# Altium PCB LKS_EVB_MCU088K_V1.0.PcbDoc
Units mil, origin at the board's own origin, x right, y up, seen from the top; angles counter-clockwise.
Board outline 2625 x 1560 mil, 2 copper layers (Top Layer, Bottom Layer); 36 components, 61 nets, 173 pads, 60 vias.
Unrouted connection lines stored in the file: 4.
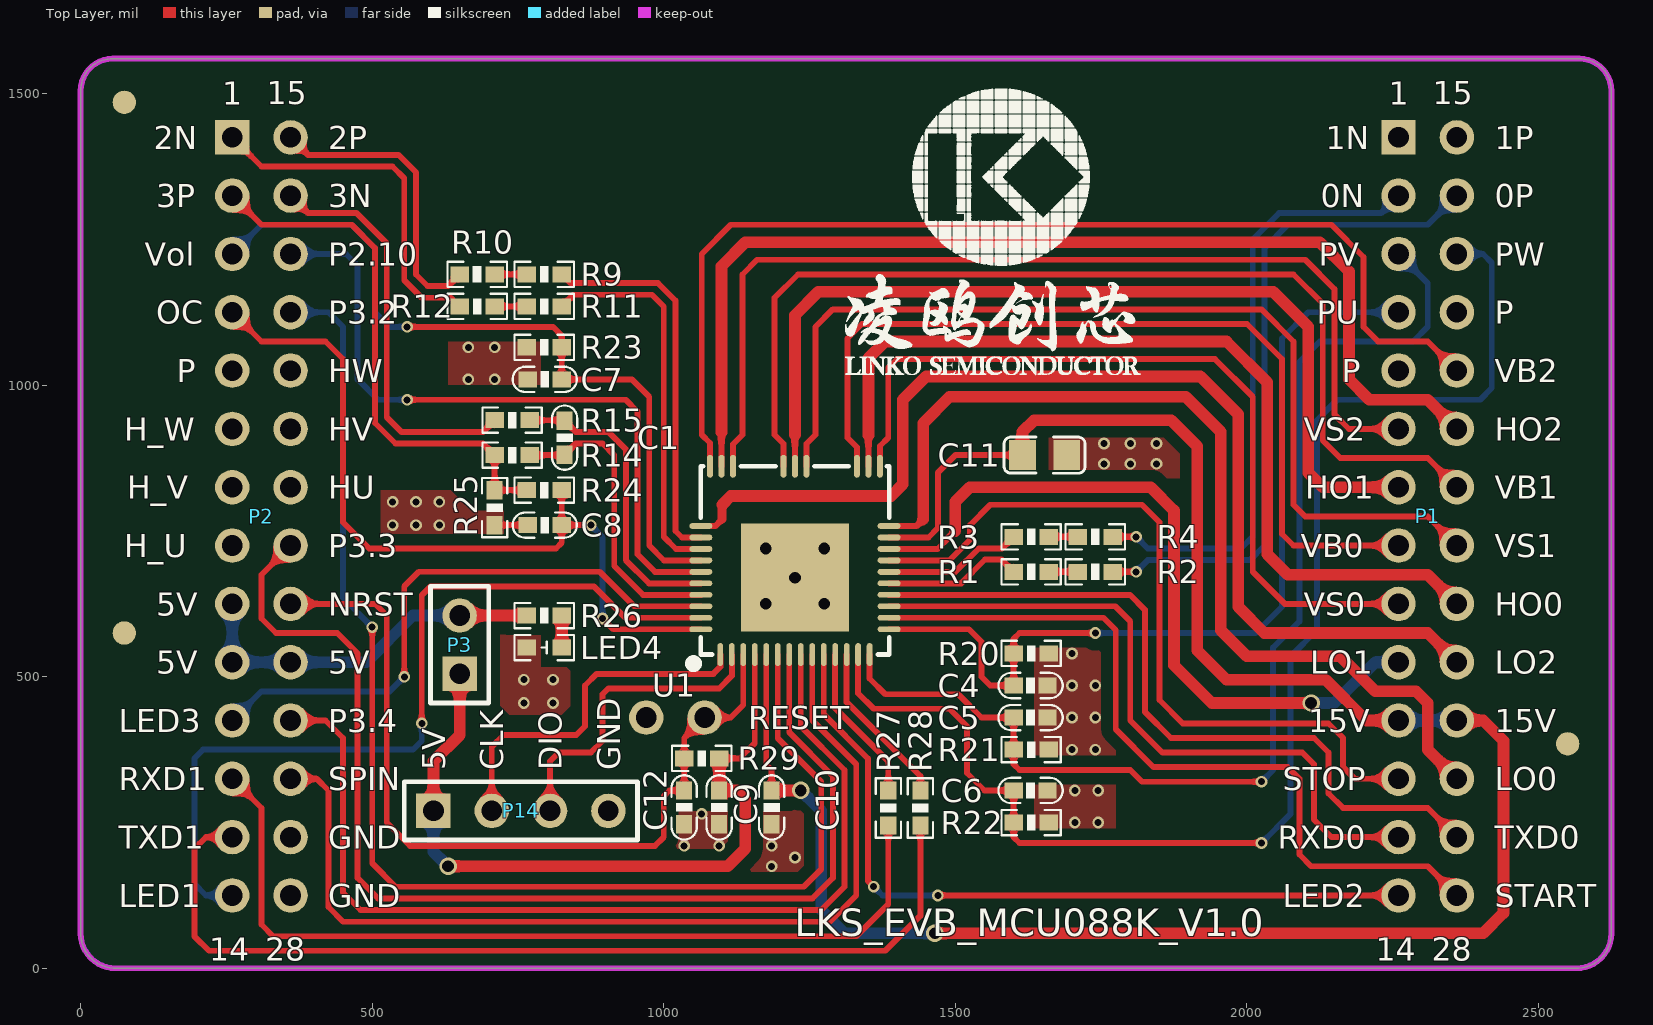
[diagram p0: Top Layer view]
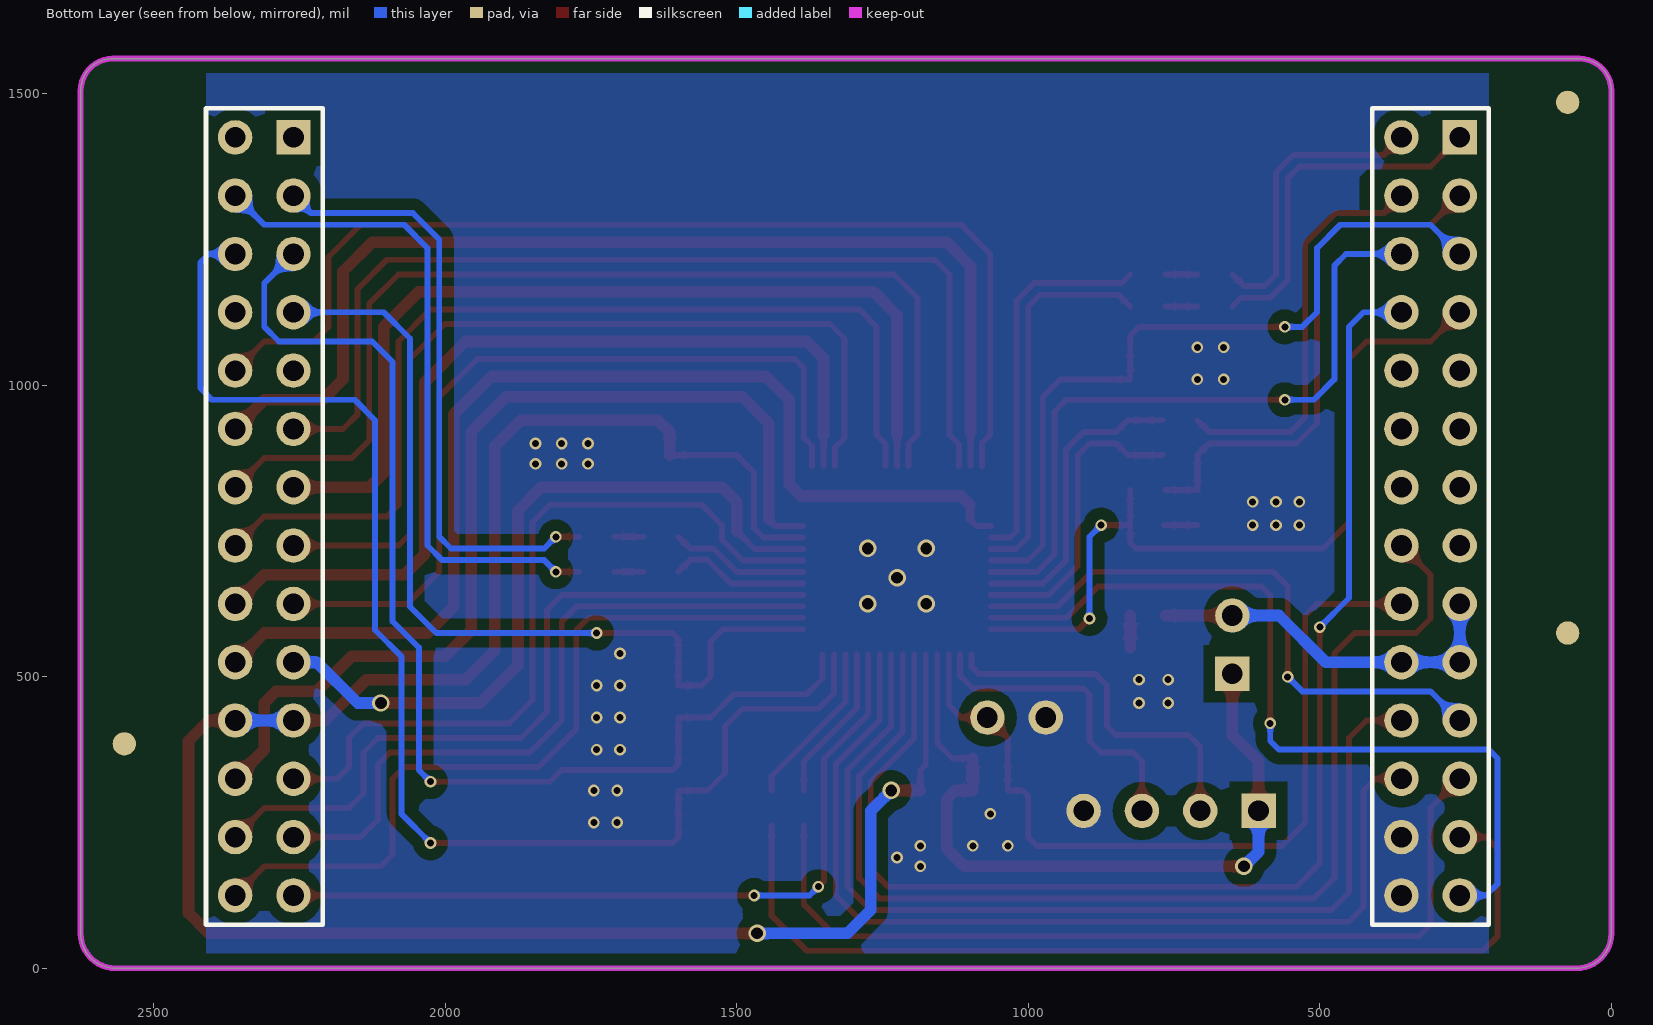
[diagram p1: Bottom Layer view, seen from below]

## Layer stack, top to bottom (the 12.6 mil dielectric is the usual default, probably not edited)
Top Solder: solder mask 0.4, Solder Resist, Dk 3.5
Top Layer: signal copper 1.4
Dielectric1: dielectric 12.6, FR-4, Dk 4.8
Bottom Layer: signal copper 1.4
Bottom Solder: solder mask 0.4, Solder Resist, Dk 3.5

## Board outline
0,60 0,1505 cw(c55,1505) 55,1560 2570,1560 cw(c2570,1505) 2625,1505 2625,60 cw(c2565,60) 2565,0 60,0 cw(c60,60)

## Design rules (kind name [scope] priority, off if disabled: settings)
Clearance Clearance_2 [InPolygon] p1: gap=20 ignorepadtopadclearanceinfootprint=FALSE
Clearance Clearance_1 [All] p2: gap=0 ignorepadtopadclearanceinfootprint=FALSE
ComponentClearance [All] p1: gap=0 collisioncheckmode=3 verticalgap=0 showdistances=FALSE
FabricationTestpoint [(IsPad And (OnTopLayer Or OnBottomLayer))] p1: side=3 testpointundercomponent=TRUE minsize=40 maxsize=100 preferedsize=60 minholesize=0 maxholesize=40 preferedholesize=32 testpointgrid=1 allowsidetop=TRUE allowsidebottom=TRUE usegrid=TRUE gridtolerance=0.01
PolygonConnect [All] p1: connectstyle=Direct reliefconductorwidth=10 reliefentries=4 polygonreliefangle="90 Angle" airgapwidth=10
RoutingVias [All] p1: holewidth=28 width=50 viastyle="Through Hole" minholewidth=0 minwidth=20 maxholewidth=28 maxwidth=50
SilkToSolderMaskClearance SilkscreenOverComponentPads [IsPad] p1: minsilkscreentomaskgap=10 clearancetoexposedcopper=TRUE
SolderMaskExpansion [All] p1: expansion=4 istentingtop=FALSE
Width [All] p1: maxlimit=50 minlimit=10 preferedwidth=10
27 further rules are at their usual default settings.

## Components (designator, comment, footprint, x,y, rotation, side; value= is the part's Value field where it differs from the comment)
C1 "1nF/50V" 0603C 830,910 r90 top
C4 "1nF/50V" 0603C 1629,485 r0 top
C5 "1nF/50V" 0603C 1629,430 r0 top
C6 "1nF/50V" 0603C 1629,305 r0 top
C7 "100nF/50V" 0603C 795.95,1010 r0 top
C8 "1nF/50V" 0603C 795.95,760 r0 top
C9 "1uF/50V" 0603C 1095,275.95 r90 top
C10 "1uF/50V" 0603C 1185,275.95 r90 top
C11 "10uF/35V" 0805C 1653,880 r180 top
C12 "100nF/50V" 0603C 1035,276 r270 top
LED4 "LED" "LED 0603R" 795,550 r0 top
P1 "2X14" "HDR 2X14 底层" 2360,1425 r0 top
P2 "2X14" "HDR 2X14 底层" 360,1425 r0 top
P3 "Header 2" "HDR 1X2" 650,505 r90 top
P14 "Header 4" "HDR 1X4" 605,270 r0 top
R1 "20K1%" 0603R 1630,680 r180 top value=K
R2 "20K1%" 0603R 1740,680 r180 top value=K
R3 "20K1%" 0603R 1630,740 r180 top value=K
R4 "20K1%" 0603R 1740,740 r180 top value=K
R9 "20K1%" 0603R 795,1190 r0 top value=K
R10 "20K1%" 0603R 680,1190 r0 top value=K
R11 "20K1%" 0603R 795,1135 r0 top value=K
R12 "20K1%" 0603R 680,1135 r0 top value=K
R14 "1K1%" 0603R 740,880 r0 top value=K
R15 "1K1%" 0603R 740,940 r0 top value=K
R20 "1K" 0603R 1630,540 r0 top value=K
R21 "1K" 0603R 1630,375 r0 top value=K
R22 "1K" 0603R 1630,250 r0 top value=K
R23 "1K1%" 0603R 795,1065 r0 top value=K
R24 "1K1%" 0603R 795,820 r180 top value=K
R25 "10R" 0603R 710,790 r270 top value=10
R26 "330R" 0603R 795,605 r0 top value=330
R27 "10R" 0603R 1385,275 r270 top
R28 "10R" 0603R 1440,275 r90 top value=100R
R29 "20K" 0603R 1065,360 r180 top value=K
U1 "LKS32MC088KU8Q8" QFN43 1225,699.53 r90 top

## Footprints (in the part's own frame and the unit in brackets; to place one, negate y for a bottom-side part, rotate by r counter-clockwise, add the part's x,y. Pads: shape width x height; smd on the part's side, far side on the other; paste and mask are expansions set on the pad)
0603C [mm] "电容"
  rect 0.8x0.7 smd: 1(-0.737,0) 2(0.738,0)
  silkscreen extent -1.4,-0.55 1.4,0.55, body extent -0.8,-0.41 0.8,0.41, height 0.81
0603R [mm] "电阻"
  rect 0.8x0.7 smd: 1(-0.762,0) 2(0.762,0)
  silkscreen extent -1.3,-0.55 1.3,0.55, body extent -0.8,-0.4 0.8,0.4, height 0.45
0805C [mil] "电容"
  rect 46x51.18 smd: 1(-38,0) 2(38,0)
  silkscreen extent -69,-31 70,31, body extent -39,-24 39,24, height 20
"HDR 1X2" [mm] "单排针 2.54mm"
  rect 1.5x1.5 hole 0.9: 1(0,0)
  round 1.5 hole 0.9: 2(2.54,0)
  silkscreen extent -1.27,-1.27 3.81,1.27, body extent -1.27,-1.27 3.81,1.27, height 8.5
"HDR 1X4" [mm] "单排针 2.54mm"
  rect 1.5x1.5 hole 0.9: 1(0,0)
  round 1.5 hole 0.9: 2(2.54,0) 3(5.08,0) 4(7.62,0)
  silkscreen extent -1.27,-1.27 8.89,1.27, body extent -1.27,-1.27 8.89,1.27, height 8.5
"HDR 2X14 底层" [mm] "双排针 2.54mm 底层"
  rect 1.5x1.5 hole 0.9: 1(-2.54,0)
  round 1.5 hole 0.9: 2(-2.54,-2.54) 3(-2.54,-5.08) 4(-2.54,-7.62) 5(-2.54,-10.16) 6(-2.54,-12.7) 7(-2.54,-15.24) 8(-2.54,-17.78) 9(-2.54,-20.32) 10(-2.54,-22.86) 11(-2.54,-25.4) 12(-2.54,-27.94) 13(-2.54,-30.48) 14(-2.54,-33.02) 15(0,0) 16(0,-2.54) 17(0,-5.08) 18(0,-7.62) 19(0,-10.16) 20(0,-12.7) 21(0,-15.24) 22(0,-17.78) 23(0,-20.32) 24(0,-22.86) 25(0,-25.4) 26(0,-27.94) 27(0,-30.48) 28(0,-33.02)
  body extent -3.81,-34.29 1.27,1.27, height 8.5
"LED 0603R" [mm] "LED"
  rect 0.8x0.7 smd: 1(0.762,0) 2(-0.762,0)
  silkscreen extent -1.3,-0.55 1.3,0.55, body extent -0.8,-0.4 0.8,0.4, height 0.47
QFN43 [mm] "088K-MCU"
  rect 4.7x4.7 smd: 0(-0.75,0)
  oval 1x0.25 smd: 1(-4.1,3.25) 2(-4.1,2.75) 3(-4.1,2.25) 4(-4.1,1.75) 5(-4.1,1.25) 6(-4.1,0.75) 7(-4.1,0.25) 8(-4.1,-0.25) 9(-4.1,-0.75) 10(-4.1,-1.25) 11(-4.1,-1.75) 12(-4.1,-2.25) 13(-4.1,-2.75) 14(-4.1,-3.25) 25(4.1,-3.7) 26(4.1,-3.2) 27(4.1,-2.7) 28(4.1,-0.5) 29(4.1,0) 30(4.1,0.5) 31(4.1,2.7) 32(4.1,3.2) 33(4.1,3.7)
  oval 0.25x1 smd: 15(-3,-4.1) 16(-2.5,-4.1) 17(-2,-4.1) 18(-1.5,-4.1) 19(-1,-4.1) 20(-0.5,-4.1) 21(0,-4.1) 22(0.5,-4.1) 23(1,-4.1) 24(1.5,-4.1) 34(1.5,4.1) 35(1,4.1) 36(0.5,4.1) 37(0,4.1) 38(-0.5,4.1) 39(-1,4.1) 40(-1.5,4.1) 41(-2,4.1) 42(-2.5,4.1) 43(-3,4.1)
  silkscreen extent -4.61,-4.1 4.1,4.53, body extent -4,-4 4,4, height 0.88

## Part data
C1 C7 C8 C9 C10 C11 C12: library part C, "Capacitor"
C4 C5 C6: library part CAP, "Capacitor"
LED4: "LED_Light"
P1 P2: "双排针"
P3: "Header, 2-Pin"
P14: "Header, 4-Pin"
R1 R2 R3 R4 R9 R10 R11 R12 R14 R15 R20 R21 R22 R23 R24 R25 R26 R29: library part Res, "Resistor"
R27 R28: library part Res2, "Resistor"
U1: "芯片"

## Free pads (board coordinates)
  round 40 all layers, no hole: 0(75,575) 0(75,1485) 0(2550,385)
  round 59.06 hole 35.43: 0(1070,430) 1(970,430)

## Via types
v1: diameter 20, hole 12, Top Layer to Bottom Layer, 51 vias
v2: diameter 30, hole 20, Top Layer to Bottom Layer, 9 vias

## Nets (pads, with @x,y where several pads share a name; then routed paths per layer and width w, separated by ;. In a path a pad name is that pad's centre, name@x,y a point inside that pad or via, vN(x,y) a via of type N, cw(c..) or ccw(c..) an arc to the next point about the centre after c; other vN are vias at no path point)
5V: C9.2 P3.1 P14.1 R29.1 U1.4 | length 1296.6
  Top Layer w10: R29.1 1130,360 1156.1,386.1 U1.4
  Top Layer w20: P14.1 605,355 650,400 P3.1 ; v2(630,175) 1110,175 1140,205 1140,290 1125,305 C9.2 R29.1
  Bottom Layer w20: P14.1 605,200 v2(630,175)
+5V: P2.9 P2.10 P2.24 P3.2 R26.1 | length 638.1
  Top Layer w20: P3.2 R26.1
  Bottom Layer w20: P2.9 P2.10 P2.24 490,525 570,605 P3.2
+15V: C10.2 C11.2 P1.11 P1.25 U1.5 U1.23 | length 3651.3
  Top Layer w10: U1.5 1175.79,349.21 1185,340 C10.2 ; U1.23 1453.9,738.9 1470,755 1470,850 1500,880 C11.2
  Top Layer w20: C10.2 v2(1235,305) ; v2(1465,60) 2405,60 2440,95 2440,390 2405,425 P1.25 ; C11.2 1615,920 1635,940 1870,940 1915,895 1915,545 1965,495 2135,495 2205,425 P1.11
  Bottom Layer w20: v2(1235,305) 1270,270 1270,100 1310,60 v2(1465,60) ; P1.11 P1.25
GND: C4.2 C5.2 C6.2 C7.1 C8.1 C9.1 C10.1 C11.1 C12.2 LED4.2 P2.16 P2.27 P2.28 P14.4 pad.1 R15.1 R20.2 R21.2 R22.2 R23.1 R25.2 U1.0 | length 757.7
  Top Layer w10: P2.16 390,1295 473.28,1295 525,1243.28 525,945 550,920 690,920 R15.1 ; R25.2 C8.1
  other v1: 1185,175 1225,190 1035,210 1095,210 1185,210 1705,250 1745,250 1065,265 1705,305 1745,305 1700,375 1740,375 1700,430 1740,430 760,455 810,455 1700,485 1740,485 760,495 810,495 1700,540 535,760 575,760 615,760 535,800 575,800 615,800 1755,865 1800,865 1845,865 1755,900 1800,900 1845,900 665,1010 710,1010 665,1065 710,1065
  other v2: 1175,625 1275,625 1225,670 1175,720 1275,720
HALL_U: P2.8
HALL_V: P2.7
HALL_W: P2.6
HO0: P1.23 U1.26 | length 1565.3
  Top Layer w10: U1.26 1350.98,914.02
  Top Layer w20: 1350.98,914.02 1350.98,1045.98 1380,1075 1965,1075 2035,1005 2035,710 2070,675 2310,675 P1.23
HO1: P1.7 U1.29 | length 1595.8
  Top Layer w10: U1.29 1225,915
  Top Layer w20: 1225,915 1225,1120 1265,1160 2045,1160 2105,1100 2105,850 2130,825 P1.7
HO2: P1.20 U1.32 | length 1862
  Top Layer w10: U1.32 1099.02,919.02
  Top Layer w20: 1099.02,919.02 1099.02,1204.02 1140,1245 2125,1245 2175,1195 2175,1010 2210,975 2310,975 P1.20
HU: P2.21
HV: P2.20
HW: P2.19
LED1: P2.14 U1.42 | length 1447.8
  Top Layer w10: v1(585,420) 585,640 600,655 880,655 933.9,601.1 U1.42
  Bottom Layer w10: P2.14 215,125 195,145 195,360.01 209.99,375 570,375 585,390 v1(585,420)
LED2: P1.14 U1.10 | length 1339.9
  Top Layer w10: U1.10 1274.21,435.79 1350,360 1350,150 v1(1360,140) ; v1(1470,125) P1.14
  Bottom Layer w10: v1(1360,140) 1375,125 v1(1470,125)
LED3: P2.11 U1.41 | length 1024.5
  Top Layer w10: v1(555,500) 555,655 580,680 890,680 949.21,620.79 U1.41
  Bottom Layer w10: P2.11 310,475 530,475 v1(555,500)
LO0: P1.26 U1.24 | length 1679.3
  Top Layer w10: U1.24 1433.58,758.58 1445,770
  Top Layer w20: 1445,770 1445,935 1490,980 1895,980 1955,920 1955,580 2000,535 2160,535 2220,475 2290,475 2310,455 2310,375 P1.26
LO1: P1.10 U1.22 | length 1284.2
  Top Layer w10: U1.22 1469.21,719.21 1500,750
  Top Layer w20: 1500,750 1500,800 1525,825 1835,825 1875,785 1875,520 1940,455 v2(2110,455)
  Bottom Layer w20: v2(2110,455) 2150,455 2220,525 P1.10
LO2: P1.24 U1.34 | length 1898.5
  Top Layer w10: U1.34 1088.58,758.58 1100,770
  Top Layer w15: 1100,770 1100,795
  Top Layer w20: 1100,795 1115,810 1390,810 1410,830 1410,975 1450,1015 1920,1015 1985,950 1985,620 2030,575 2310,575 P1.24
NetLED4_1: LED4.1 R26.2 | length 55
  Top Layer w20: LED4.1 R26.2
NetR1_1: R1.1 R2.2 | length 50
  Top Layer w10: R1.1 R2.2
NetR3_1: R3.1 R4.2 | length 50
  Top Layer w10: R3.1 R4.2
NetR9_1: R9.1 R10.2 | length 55
  Top Layer w10: R10.2 R9.1
NetR11_1: R11.1 R12.2 | length 55
  Top Layer w10: R12.2 R11.1
NetR27_1: R27.1 U1.11 | length 270.8
  Top Layer w10: U1.11 1293.9,446.1 1385,355 R27.1
NetR28_2: R28.2 U1.12 | length 285.5
  Top Layer w10: U1.12 1313.58,456.42 1440,330 R28.2
NRST: C12.1 P2.23 pad.0@1070,430 R29.2 U1.3 | length 1436.7
  Top Layer w10: P2.23 505,625 525,605 525,250 565,210 985,210 1000,225 1000,295 1010,305 C12.1 R29.2 1035,395 1070,430 1115,430 1136.42,451.42 U1.3
OC: C8.2 P2.4 R24.1 U1.43 | length 1385.5
  Top Layer w10: P2.4 310,1075 420,1075 450,1045 450,765 495,720 815,720 825,730 C8.2 ; R24.1 C8.2 ; v1(875,760) C8.2 ; v1(895,600) 913.58,581.42 U1.43
  Bottom Layer w10: v1(875,760) 895,740 v1(895,600)
OPA0_IN: R3.2 U1.20 | length 238.5
  Top Layer w10: U1.20 1499.84,679.84 1540,720 1580,720 R3.2
OPA0_IP: R1.2 U1.19 | length 239.2
  Top Layer w10: U1.19 1510.16,660.16 1551,701 1579,701 R1.2
OPA2_IN: R11.2 U1.36 | length 658.8
  Top Layer w10: R11.2 845,1155 980,1155 1000,1135 1000,740 1020.79,719.21 U1.36
OPA2_IP: R9.2 U1.35 | length 656.8
  Top Layer w10: R9.2 840,1175 990,1175 1020,1145 1020,750 1031.1,738.9 U1.35
OPA3_IN: C1.2 R15.2 U1.39 | length 520.8
  Top Layer w10: R15.2 829.05,940 C1.2 849.05,920 905,920 935,890 935,700 974.84,660.16 U1.39
OPA3_IP: C1.1 R14.2 U1.40 | length 520.7
  Top Layer w10: R14.2 829,880 C1.1 849,900 895,900 915,880 915,690 964.53,640.47 U1.40
P2.10: P2.17 U1.38 | length 1187.1
  Top Layer w10: v1(560,975) 935,975 955,955 955,710 985.16,679.84 U1.38
  Bottom Layer w10: P2.17 455,1225 475,1205 475,1010 510,975 v1(560,975)
P3.2: P2.18 U1.6 | length 2239
  Top Layer w10: v1(500,585) 500,180 540,140 1240,140 1270,170 1270,320 1195.47,394.53 U1.6
  Bottom Layer w10: P2.18 425,1125 450,1100 450,635 v1(500,585)
P3.3: P2.22 U1.7 | length 1978.7
  Top Layer w10: P2.22 310,675 310,600 335,575 440,575 475,540 475,155 510,120 1255,120 1290,155 1290,330 1215.16,404.84 U1.7
P3.4: P2.25 U1.8 | length 1685.7
  Top Layer w10: P2.25 420,425 450,395 450,130 480,100 1270,100 1310,140 1310,340 1234.84,415.16 U1.8
PGND: P1.1 P1.2 P2.1 P2.2 R4.1 R12.1 R14.1 R24.2 R25.1 | length 2585.3
  Top Layer w10: P2.2 310,1275 465,1275 505,1235 505,935 540,900 690,900 R14.1 R25.1 R24.2 ; P2.1 310,1375 535,1375 555,1355 555,1180 585,1150 635,1150 R12.1 ; R4.1 v1(1810,740)
  Bottom Layer w10: v1(1810,740) 1830,720 1990,720 2010,740 2010,1250 2055,1295 2230,1295 P1.2
PU: C4.1 P1.4 R20.1 U1.15 | length 1530.1
  Top Layer w10: U1.15 1523.58,581.42 1545,560 1545,500 1560,485 C4.1 R20.1 1600,565 1610,575 v1(1740,575)
  Bottom Layer w10: v1(1740,575) 2015,575 2060,620 2060,1080 2105,1125 P1.4
PV: C5.1 P1.3 R21.1 U1.14 | length 1970.8
  Top Layer w10: U1.14 1352.95,497.05 1380,470 1505,470 1545,430 C5.1 R21.1 1600,350 1610,340 1800,340 1820,320 v1(2025,320)
  Bottom Layer w10: v1(2025,320) 2045,340 2045,550 2090,595 2090,1040 2125,1075 2285,1075 2309.99,1099.99 2309.99,1175.01 P1.3
PW: C6.1 P1.17 R22.1 U1.13 | length 2326.5
  Top Layer w10: U1.13 1333.27,471.73 1360,445 1490,445 1520,415 1520,335 1550,305 C6.1 R22.1 1600,225 1610,215 v1(2025,215)
  Bottom Layer w10: v1(2025,215) 2075,265 2075,535 2120,580 2120,940 2155,975 2400,975 2420,995 2420,1210 2405,1225 P1.17
RXD0: P1.13 U1.17 | length 1192.8
  Top Layer w10: U1.17 1774.21,620.79 1800,595 1800,425 1855,370 2095,370 2115,350 2115,255 2145,225 P1.13
RXD1: P2.12 R27.2 | length 1511.8
  Top Layer w10: P2.12 310,275 310,75 330,55 1330,55 1385,110 R27.2
SPIN: P2.26 U1.9 | length 1651.7
  Top Layer w10: P2.26 405,325 425,305 425,105 450,80 1285,80 1330,125 1330,350 1254.53,425.47 U1.9
START1: P1.28 U1.16 | length 1346.5
  Top Layer w10: U1.16 1753.9,601.1 1775,580 1775,410 1840,345 2070,345 2090,325 2090,195 2110,175 2310,175 P1.28
STOP1: P1.12 U1.21 | length 1330.4
  Top Layer w10: U1.21 1489.53,699.53 1525,735 1525,760 1560,795 1820,795 1850,765 1850,460 1890,420 2140,420 2165,395 2165,345 2185,325 P1.12
SWCLK: P14.2 U1.1 | length 620.9
  Top Layer w10: P14.2 705,380 725,400 850,400 865,415 865,485 885,505 1085,505 1097.05,517.05 U1.1
SWDIO: P14.3 U1.2 | length 540.8
  Top Layer w10: P14.3 805,355 820,370 875,370 895,390 895,470 905,480 1095,480 1116.73,501.73 U1.2
TXD0: P1.27 U1.18 | length 1289.2
  Top Layer w10: U1.18 1799.53,640.47 1825,615 1825,440 1870,395 2115,395 2140,370 2140,300 2165,275 2310,275 P1.27
TXD1: P2.13 R28.1 | length 1658.5
  Top Layer w10: P2.13 215,225 195,205 195,55 220,30 1380,30 1440,90 R28.1
UP-: P2.15 R10.1 | length 506.4
  Top Layer w10: P2.15 390,1395 545,1395 575,1365 575,1190 595,1170 630,1170 R10.1
VB0: P1.8 U1.27 | length 1514.3
  Top Layer w10: U1.27 1331.3,893.7 1315,910 1315,1080 1340,1105 2000,1105 2060,1045 2060,745 2080,725 P1.8
VB1: P1.21 U1.30 | length 1770.8
  Top Layer w10: U1.30 1205.32,899.68 1190,915 1190,1150 1230,1190 2080,1190 2130,1140 2130,905 2160,875 2310,875 P1.21
VB2: P1.19 U1.33 | length 1859.5
  Top Layer w10: U1.33 1079.33,900.67 1065,915 1065,1225 1115,1275 2145,1275 2200,1220 2200,1100 2225,1075 2310,1075 P1.19
VOL_ADC: C7.2 P2.3 R23.2 U1.37 | length 1320.4
  Top Layer w10: v1(560,1100) 810,1100 825,1085 R23.2 C7.2 945,1010 975,980 975,725 1000.47,699.53 U1.37
  Bottom Layer w10: P2.3 310,1275 465,1275 505,1235 505,1125 530,1100 v1(560,1100)
VP-: P1.15
VS0: P1.9 U1.25 | length 1405.9
  Top Layer w10: U1.25 1370.67,895.67 1385,910 1385,1030 1400,1045 1945,1045 2010,980 2010,680 2065,625 P1.9
VS1: P1.22 U1.28 | length 1689.6
  Top Layer w10: U1.28 1244.69,899.69 1260,915 1260,1100 1290,1130 2025,1130 2080,1075 2080,795 2100,775 2310,775 P1.22
VS2: P1.6 U1.31 | length 1717.2
  Top Layer w10: U1.31 1118.7,898.7 1135,915 1135,1190 1160,1215 2100,1215 2150,1165 2150,950 2175,925 P1.6
WP-: P1.16 R2.1 | length 1155.9
  Top Layer w10: R2.1 v1(1810,680)
  Bottom Layer w10: v1(1810,680) 1830,700 2005,700 2030,725 2030,1235 2070,1275 2310,1275 P1.16
pads on no net: P1.5 P1.18 P2.5

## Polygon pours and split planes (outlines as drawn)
GND on Top Layer "NONET_L-01_P-001" (solid, remove dead copper, pour order 21): 650,1100 630,1080 630,995 650,975 795,975 795,1100
GND on Top Layer "NONET_L-01_P-001" (solid, remove dead copper, pour order 20): 515,820 635,820 665,790 725.76,790 725.76,745.76 715,735 515,735
GND on Top Layer "NONET_L-01_P-001" (solid, remove dead copper, pour order 19): 720,571.65 790,571.65 790,535.32 805.32,520 830,520 840,510 840,450 825,435 735,435 720,450
GND on Top Layer "NONET_L-01_P-001" (solid, remove dead copper, pour order 18): 1000,280 1225,280 1240,265 1240,155 1225,140 1000,140
GND on Top Layer "NONET_L-01_P-001" (solid, remove dead copper, pour order 17): 1635,575 1635,215 1775,215 1775,575
GND on Top Layer "NONET_L-01_P-001" (solid, remove dead copper, pour order 16): 1660,920 1890,920 1915,895 1915,840 1660,840
GND on Bottom Layer "Bottom Layer-No Net 1" (solid, remove dead copper, pour order 15): 210,1560 210,0 2409.99,0 2409.99,1560

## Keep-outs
Keep-Out Layer:
  the board outline again, w10

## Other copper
Bottom Layer:
  pour cut-out: 187.14,1370 418.62,1370 432.14,1356.48 432.14,1275 187.14,1275

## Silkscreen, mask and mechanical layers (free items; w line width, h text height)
Top Overlay:
  drawing of 144 lines, arcs and shapes, not listed
  text "2N" at 125,1405 h39.37
  text "2P" at 425,1405 h39.37
  text "1N" at 2135,1405 h39.37
  text "1P" at 2425,1405 h39.37
  text "3P" at 130,1305 h39.37
  text "3N" at 425,1305 h39.37
  text "0N" at 2126.57,1305 h39.37
  text "0P" at 2425,1305 h39.37
  text "Vol" at 110,1205 h39.37
  text "P2.10" at 425,1205 h39.37
  text "PV" at 2123.38,1205 h39.37
  text "PW" at 2425,1205 h39.37
  text "OC" at 130,1105 h39.37
  text "P3.2" at 425,1105 h39.37
  text "PU" at 2119.63,1105 h39.37
  text "P" at 2425,1105 h39.37
  text "P" at 165,1005 h39.37
  text "HW" at 425,1005 h39.37
  text "P" at 2162.37,1005 h39.37
  text "VB2" at 2425,1004.65 h39.37
  text "H_W" at 75,905 h39.37
  text "HV" at 425,905 h39.37
  text "VS2" at 2097.14,905 h39.37
  text "HO2" at 2425,905 h39.37
  text "H_V" at 80,805 h39.37
  text "HU" at 425,805 h39.37
  text "HO1" at 2099.76,805 h39.37
  text "VB1" at 2425,805 h39.37
  text "H_U" at 75,705 h39.37
  text "P3.3" at 425,705 h39.37
  text "VB0" at 2092.08,705 h39.37
  text "VS1" at 2425,705 h39.37
  text "5V" at 130,605 h39.37
  text "NRST" at 425,605 h39.37
  text "VS0" at 2097.14,605 h39.37
  text "HO0" at 2425,605 h39.37
  text "5V" at 130,505 h39.37
  text "5V" at 425,505 h39.37
  text "LO1" at 2108.2,505 h39.37
  text "LO2" at 2425,505 h39.37
  text "RESET" at 1145,410 h39.37
  text "LED3" at 65,405 h39.37
  text "P3.4" at 425,405 h39.37
  text "15V" at 2104.82,405 h39.37
  text "15V" at 2425,405 h39.37
  text "5V" at 625,340 h39.37 r90
  text "CLK" at 725,340 h39.37 r90
  text "DIO" at 825,340 h39.37 r90
  text "GND" at 925,340 h39.37 r90
  text "RXD1" at 65,305 h39.37
  text "SPIN" at 425,305 h39.37
  text "STOP" at 2061.15,305 h39.37
  text "LO0" at 2425,305 h39.37
  text "TXD1" at 65,205 h39.37
  text "GND" at 425,205 h39.37
  text "RXD0" at 2053.28,205 h39.37
  text "TXD0" at 2425,205 h39.37
  text "LED1" at 65,105 h39.37
  text "GND" at 425,105 h39.37
  text "LED2" at 2061.71,105 h39.37
  text "START" at 2425,105 h39.37
  text "LKS_EVB_MCU088K_V1.0" at 1225,40 h80
Top Solder:
  circle w78: c75,575 r17
  circle w78: c2550,385 r17
  circle w78: c75,1485 r17
Mechanical 1:
  the board outline again, w10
